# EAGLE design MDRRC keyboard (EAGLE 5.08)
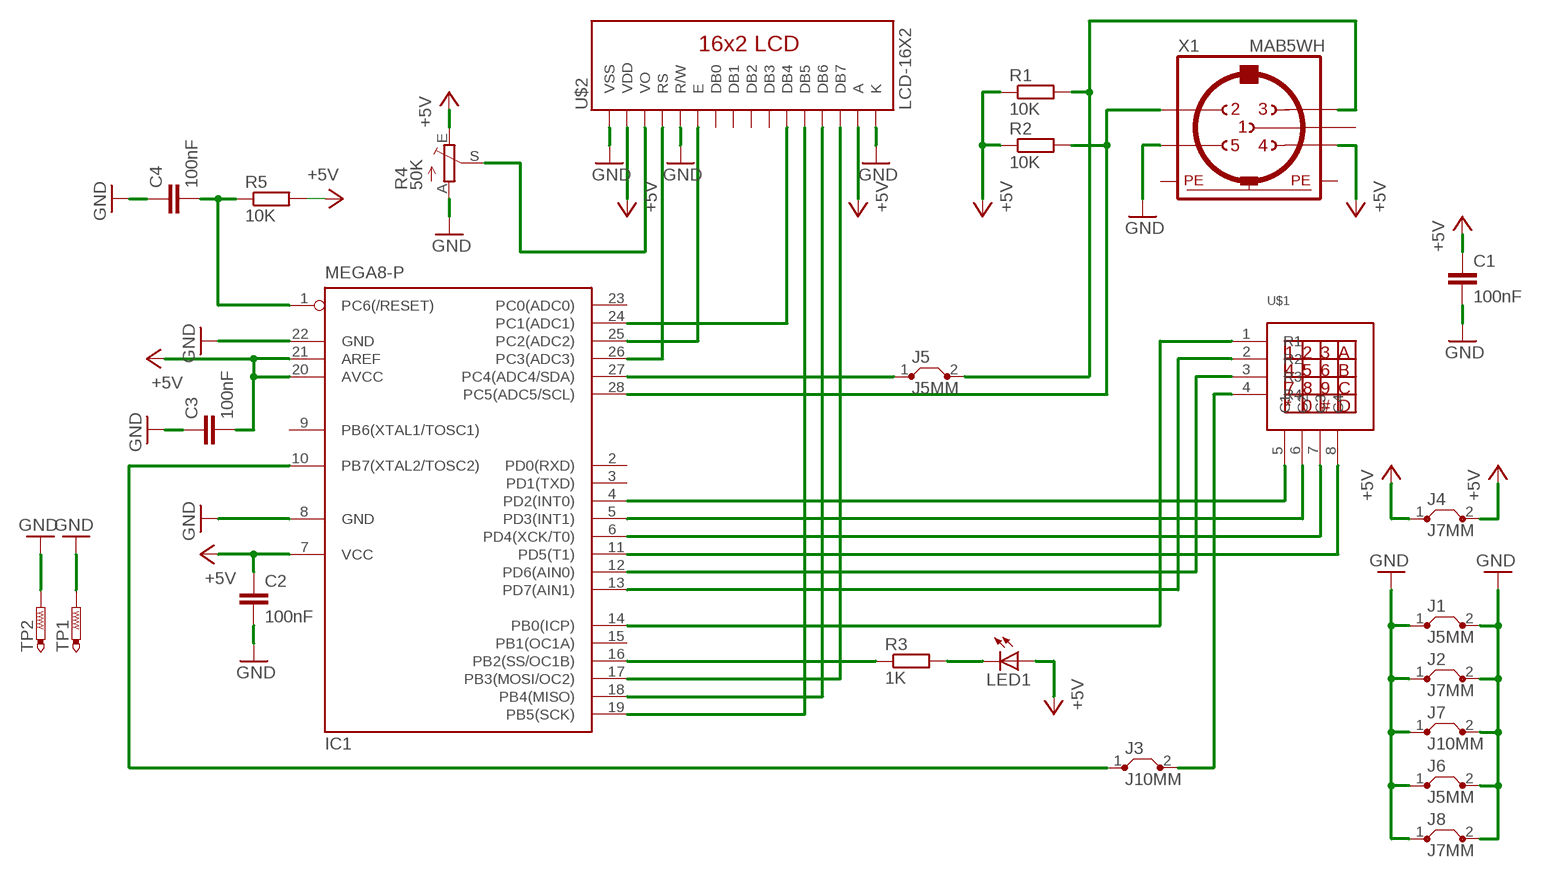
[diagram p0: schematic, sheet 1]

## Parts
C1  100nF  C-EU025-025X050  [C025-025X050]
C2  100nF  C-EU025-025X050  [C025-025X050]
C3  100nF  C-EU025-025X050  [C025-025X050]
C4  100nF  C-EU025-025X050  [C025-025X050]
IC1  MEGA8-P  [DIL28-3]
J1  J5MM  [05]
J2  J7MM  [07]
J3  J10MM  [10]
J4  J7MM  [07]
J5  J5MM  [05]
J6  J5MM  [05]
J7  J10MM  [10]
J8  J7MM  [07]
LED1  LED3MM  [LED3MM]
R1  10K  R-EU_0207/12  [0207/12]
R2  10K  R-EU_0207/12  [0207/12]
R3  1K  R-EU_0207/12  [0207/12]
R4  50K  TRIM_EU-CA6V  [CA6V]
R5  10K  R-EU_0207/15  [0207/15]
TP1  PTR1PAD1-13Y  [P1-13Y]
TP2  PTR1PAD1-13Y  [P1-13Y]
U$1  KEYPAD4X4  [KEYPAD4X4]
U$2  LCD-16X2  [LCD-16X2]
X1  MAB5WH  [MAB5WH]

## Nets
+5V: C1.1 C2.1 C3.2 IC1.7(VCC) IC1.20(AVCC) IC1.21(AREF) J4.1 J4.2 LED1.A R1.1 R2.1 R4.E R5.2 U$2.2(VDD) U$2.15(A) X1.4
GND: C1.2 C2.2 C3.1 C4.1 IC1.8(GND) IC1.22(GND) J1.1 J1.2 J2.1 J2.2 J6.1 J6.2 J7.1 J7.2 J8.1 J8.2 R4.A TP1.TP TP2.TP U$2.1(VSS) U$2.5(R/W) U$2.16(K) X1.5
N$1: IC1.14(PB0(ICP)) U$1.1(R1)
N$2: IC1.13(PD7(AIN1)) U$1.2(R2)
N$3: IC1.12(PD6(AIN0)) U$1.3(R3)
N$4: IC1.10(PB7(XTAL2/TOSC2)) J3.1
N$5: IC1.4(PD2(INT0)) U$1.5(C1)
N$6: IC1.5(PD3(INT1)) U$1.6(C2)
N$7: IC1.6(PD4(XCK/T0)) U$1.7(C3)
N$8: IC1.11(PD5(T1)) U$1.8(C4)
N$10: J5.2 R1.2 X1.3
N$11: IC1.25(PC2(ADC2)) U$2.6(E)
N$12: IC1.26(PC3(ADC3)) U$2.4(RS)
N$13: IC1.24(PC1(ADC1)) U$2.11(DB4)
N$14: IC1.19(PB5(SCK)) U$2.12(DB5)
N$15: IC1.18(PB4(MISO)) U$2.13(DB6)
N$16: IC1.17(PB3(MOSI/OC2)) U$2.14(DB7)
N$17: IC1.16(PB2(SS/OC1B)) R3.1
N$18: LED1.K(C) R3.2
N$19: R4.S U$2.3(VO)
N$20: J3.2 U$1.4(R4)
N$21: IC1.27(PC4(ADC4/SDA)) J5.1
N$22: C4.2 IC1.1(PC6(/RESET)) R5.1
N$23: IC1.28(PC5(ADC5/SCL)) R2.2 X1.2
Unconnected: IC1.2(PD0(RXD)) IC1.3(PD1(TXD)) IC1.9(PB6(XTAL1/TOSC1)) IC1.15(PB1(OC1A)) IC1.23(PC0(ADC0)) U$2.7(DB0) U$2.8(DB1) U$2.9(DB2) U$2.10(DB3) X1.1

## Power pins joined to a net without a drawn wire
PE: X1.PE X1.PE@(PE)

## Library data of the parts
C1-C4 = rcl:C-EU: CAPACITOR, European symbol
IC1 = atmel:MEGA8-P: MICROCONTROLLER 8 Kbytes FLASH, 1 kbytes SRAM, 512 bytes EEPROM, USART, 4-channel 10 bit ADC, 2-channel 8 bit ADC Pin compatible with Atmega48, ATMega88, ATMega168 Source: avr.lbr
J1-J8 = jumper:J: Bridge
LED1 = led:LED: LED
R1-R3 R5 = rcl:R-EU_: RESISTOR, European symbol
R4 = pot:TRIM_EU-: POTENTIOMETER
TP1 TP2 = testpad:PTR1: TEST PIN
U$1 = keypad4x4_ece:KEYPAD4X4
U$2 = SparkFun:LCD-16X2
X1 = con-hirschmann:MAB5WH: Female CONNECTOR 5 pins with shield, horizontal (DIN 45327)

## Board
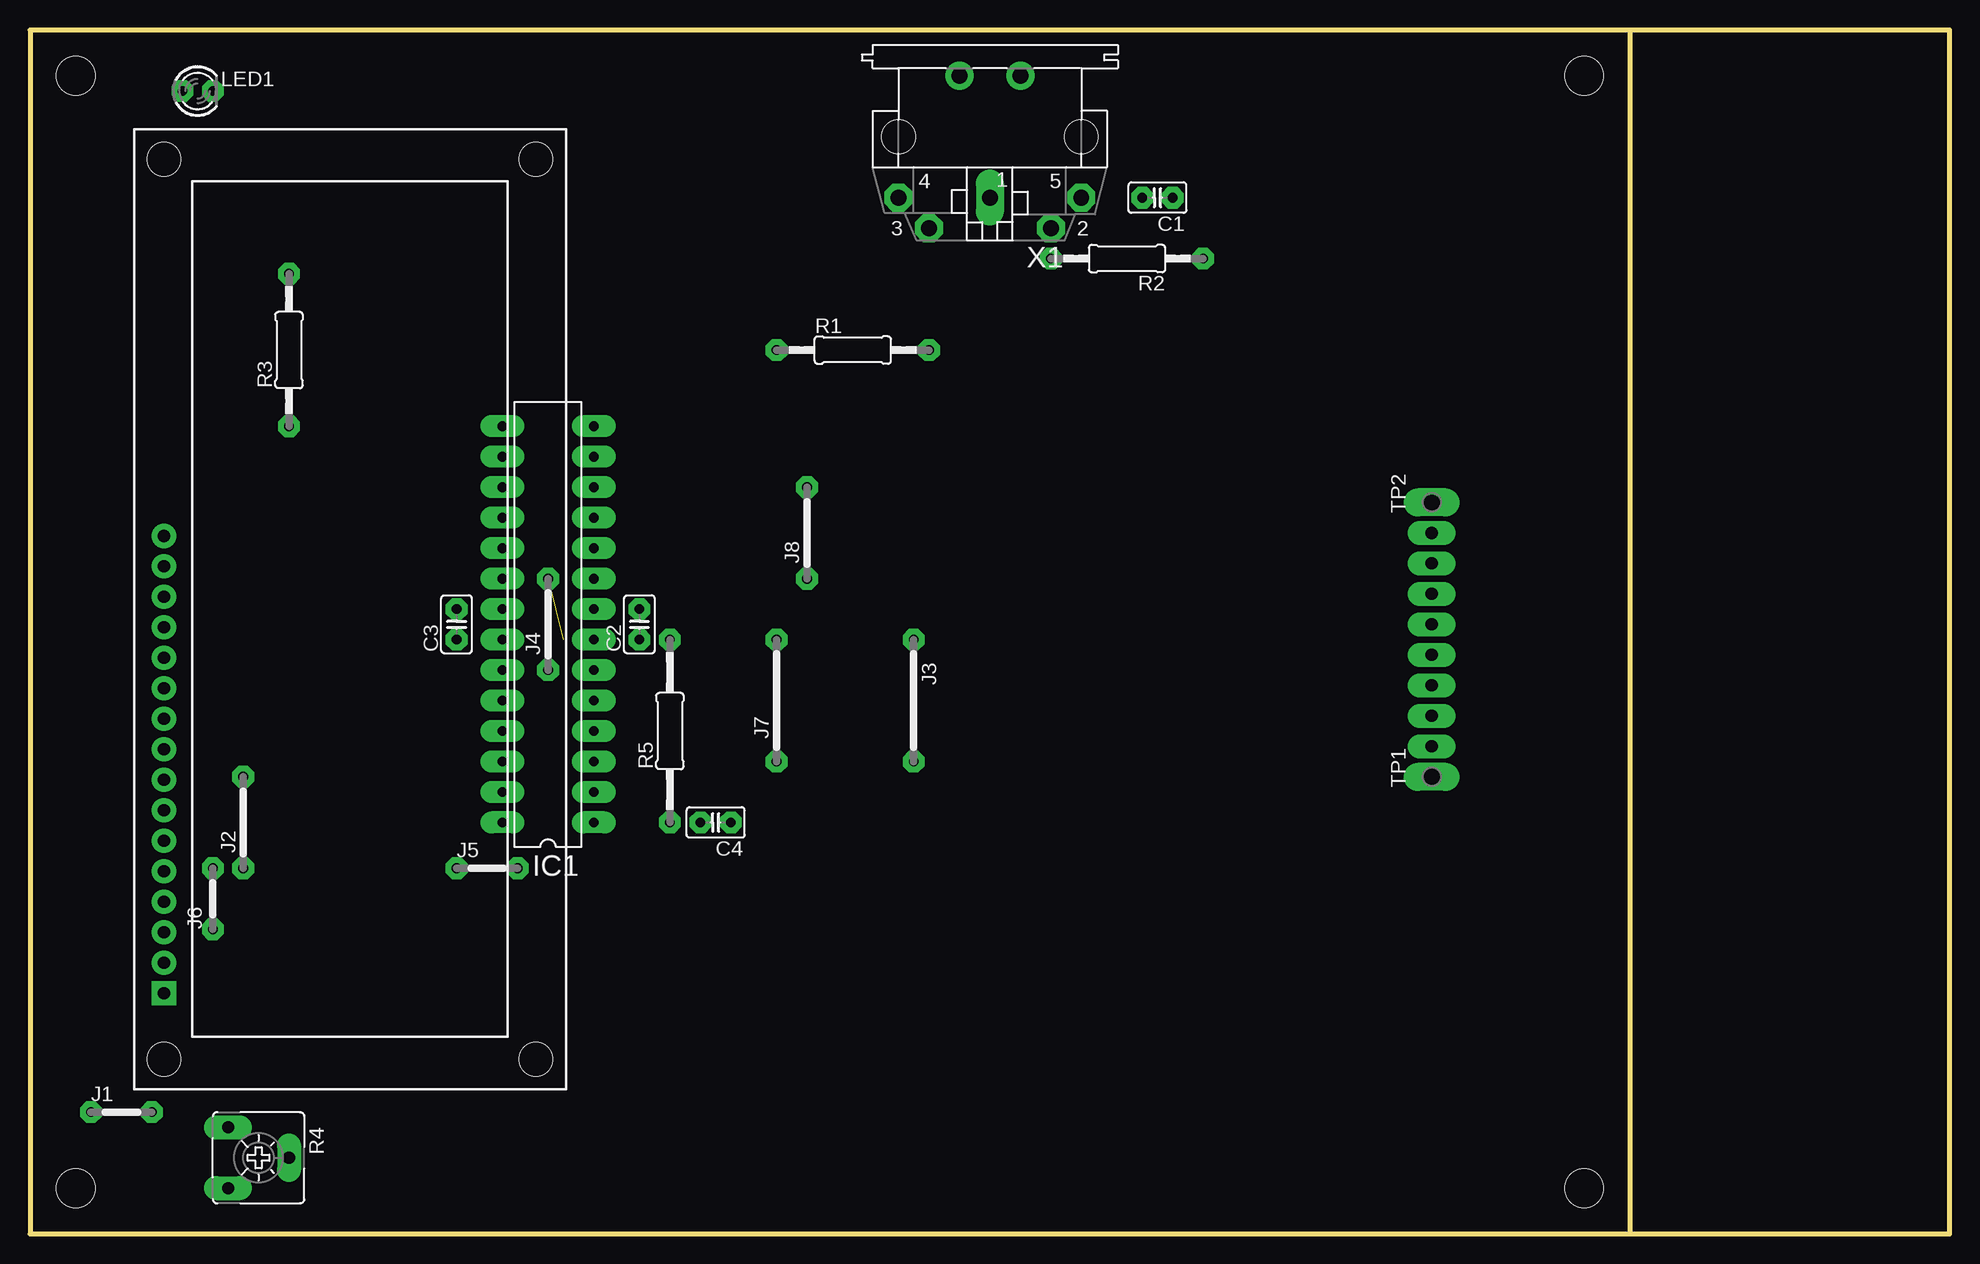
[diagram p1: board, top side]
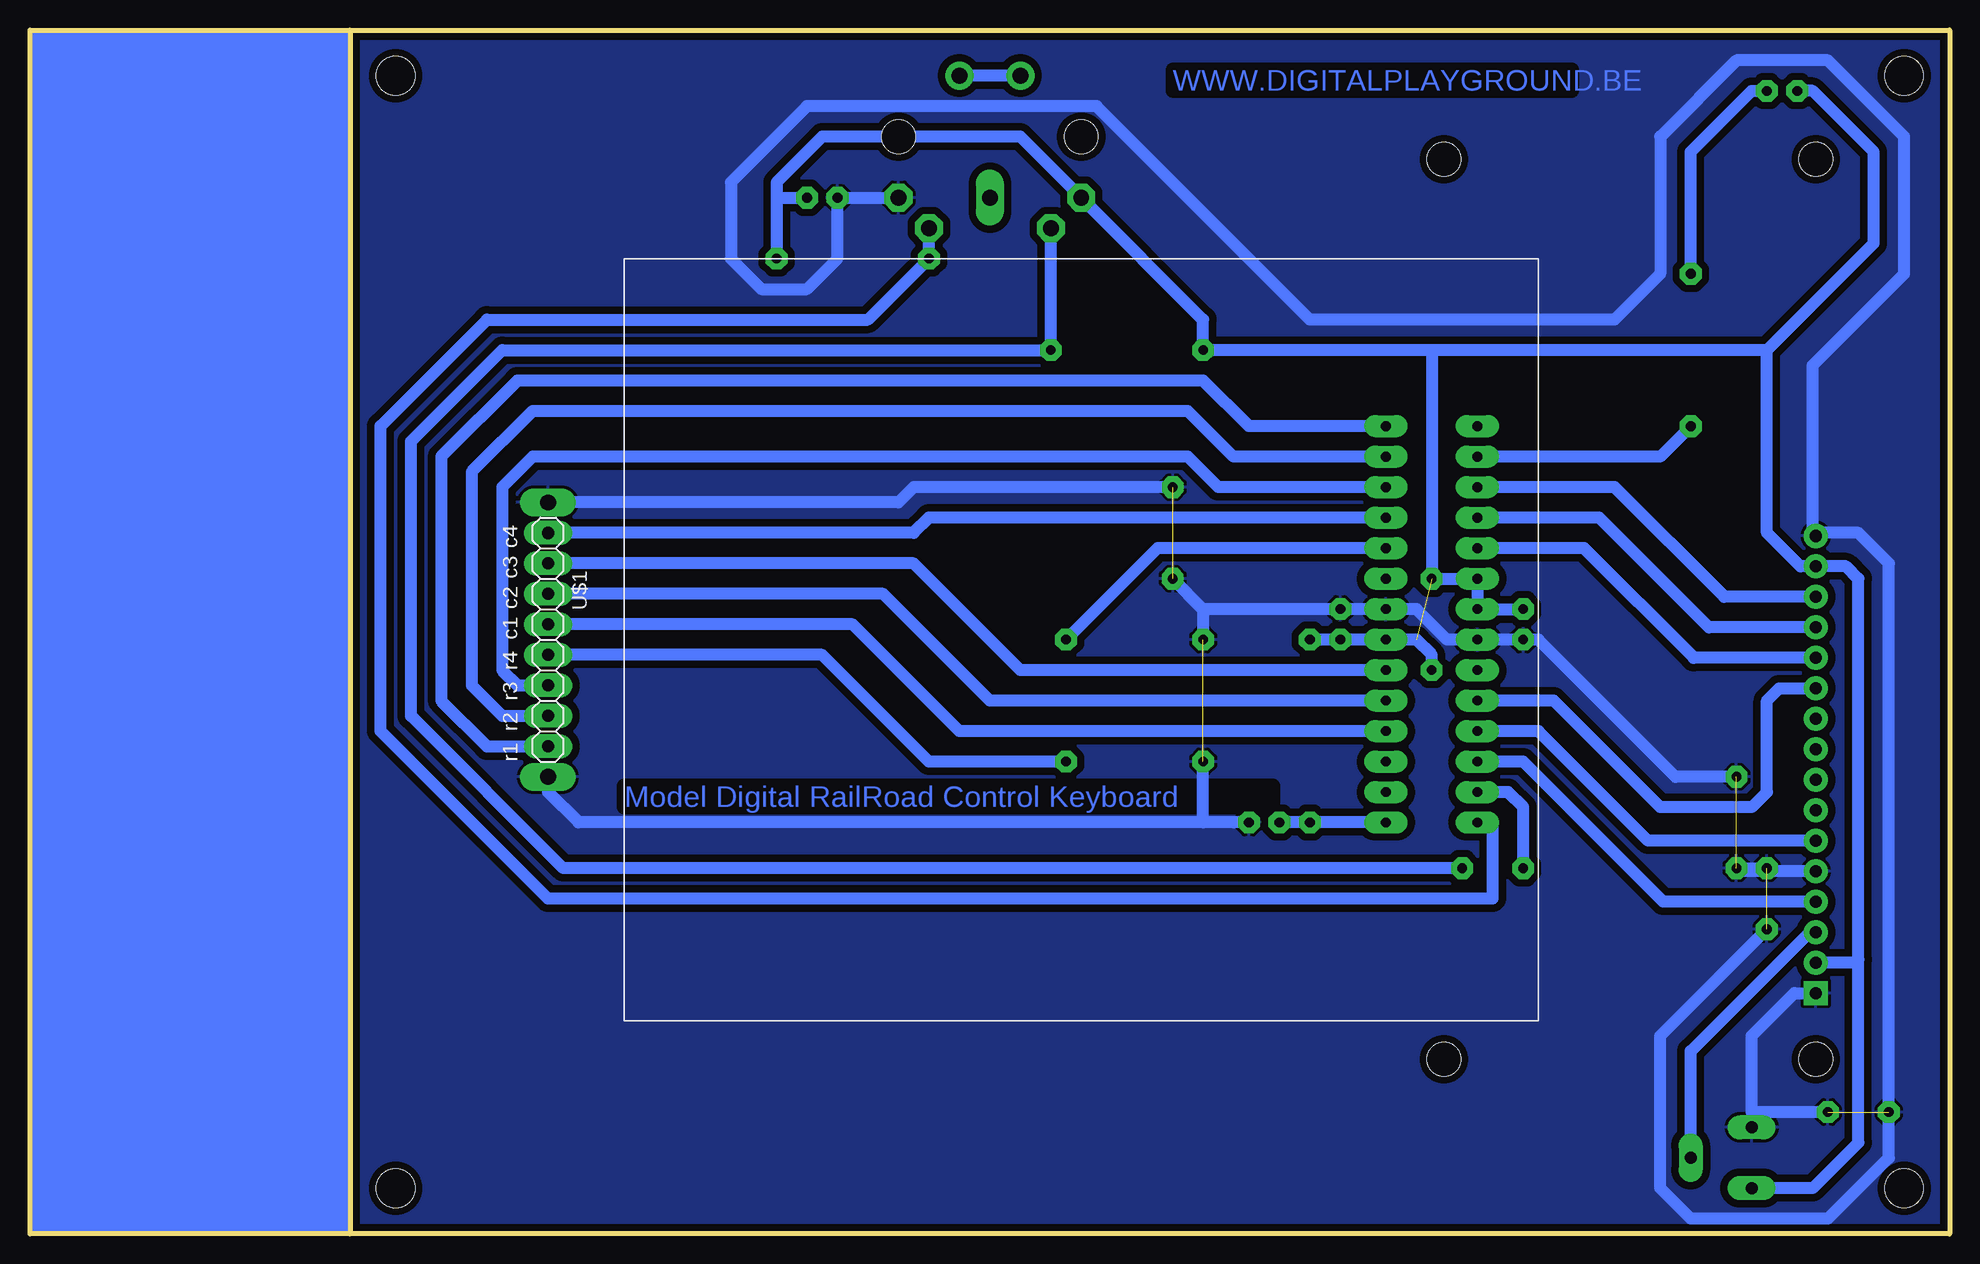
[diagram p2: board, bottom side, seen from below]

Size 160.02 x 100.33 mm. Coordinates in mm from the lower left corner, seen from the top.
Outline: 133.35,0 0,0 0,100.33 133.35,100.33
Outline: 133.35,0 160.02,0 160.02,100.33 133.35,100.33
Outline: 133.35,100.33 133.35,0
Copper layers (1*16): Top 0.8mm / dielectric 1.3mm / Bottom 0.8mm
Design rules "DRC settings smallest": minimum track width 0.8mm, minimum drill 24mil, track to track 0.2mm, track to pad 0.2mm, pad to pad 0.2mm, via to via 0.2mm, smd to smd 8mil, copper to edge 0.3mm, drill to drill 0.3mm, minimum pad ring 0.5mm, minimum via ring 1mm, stop-mask expansion 4mil, vias tented up to drill 0mil, thermal gap 10mil
Holes 3.2 mm at 3.81,96.52 3.81,3.81 129.54,96.52 129.54,3.81

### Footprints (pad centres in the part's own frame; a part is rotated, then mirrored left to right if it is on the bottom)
C025-025X050 = drill 0.813 octagon: 1 -1.27,0; 2 1.27,0
DIL28-3 = drill 0.813 long: 1 -16.51,-3.81; 2 -13.97,-3.81; 3 -11.43,-3.81; 4 -8.89,-3.81; 5 -6.35,-3.81; 6 -3.81,-3.81; 7 -1.27,-3.81; 8 1.27,-3.81; 9 3.81,-3.81; 10 6.35,-3.81; 11 8.89,-3.81; 12 11.43,-3.81; 13 13.97,-3.81; 14 16.51,-3.81; 15 16.51,3.81; 16 13.97,3.81; 17 11.43,3.81; 18 8.89,3.81; 19 6.35,3.81; 20 3.81,3.81; 21 1.27,3.81; 22 -1.27,3.81; 23 -3.81,3.81; 24 -6.35,3.81; 25 -8.89,3.81; 26 -11.43,3.81; 27 -13.97,3.81; 28 -16.51,3.81
05 = drill 0.813 pad 1.6 octagon: 1 -2.54,0; 2 2.54,0
07 = drill 0.813 pad 1.6 octagon: 1 -3.81,0; 2 3.81,0
10 = drill 0.813 pad 1.6 octagon: 1 -5.08,0; 2 5.08,0
LED3MM = drill 0.813 octagon: A -1.27,0; K 1.27,0
0207/12 = drill 0.813 octagon: 1 -6.35,0; 2 6.35,0
CA6V = drill 1.016 long: A -2.54,-2.54; E 2.54,-2.54; S 0,2.54
0207/15 = drill 0.813 octagon: 1 -7.62,0; 2 7.62,0
P1-13Y = drill 1.321 pad 1.905 long: TP 0,0
KEYPAD4X4 = drill 1.016 long: 1 -13.97,1.27; 2 -11.43,1.27; 3 -8.89,1.27; 4 -6.35,1.27; 5 -3.81,1.27; 6 -1.27,1.27; 7 1.27,1.27; 8 3.81,1.27
LCD-16X2 = drill 1.016 square: 1 -32,15.5 | drill 1.016 round: 2 -29.46,15.5; 3 -26.92,15.5; 4 -24.38,15.5; 5 -21.84,15.5; 6 -19.3,15.5; 7 -16.76,15.5; 8 -14.22,15.5; 9 -11.68,15.5; 10 -9.14,15.5; 11 -6.6,15.5; 12 -4.06,15.5; 13 -1.52,15.5; 14 1.02,15.5; 15 3.56,15.5; 16 6.1,15.5 | hole 2.8: -37.5,15.5; -37.5,-15.5; 37.5,15.5; 37.5,-15.5
MAB5WH = drill 1.321 long: 1 0,5.08 | drill 1.321 octagon: 2 -5.08,7.62; 3 5.08,7.62; 4 7.62,5.08; 5 -7.62,5.08 | drill 1.321 round: PE -2.54,-5.08; PE@ 2.54,-5.08 | hole 2.794: 7.62,0; -7.62,0

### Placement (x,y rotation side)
C1  93.98,86.36 180 top
C2  50.8,50.8 90 top
C3  35.56,50.8 90 top
C4  57.15,34.29 180 top
IC1  43.18,50.8 90 top
J1  7.62,10.16 0 top
J2  17.78,34.29 90 top
J3  73.66,44.45 270 top
J4  43.18,50.8 90 top
J5  38.1,30.48 0 top
J6  15.24,27.94 90 top
J7  62.23,44.45 90 top
J8  64.77,58.42 90 top
LED1  13.97,95.25 0 top
R1  68.58,73.66 0 top
R2  91.44,81.28 180 top
R3  21.59,73.66 90 top
R4  19.05,6.35 270 top
R5  53.34,41.91 90 top
TP1  116.84,38.1 90 top
TP2  116.84,60.96 90 top
U$1  115.57,54.61 90 bottom
U$2  26.67,52.07 90 top
X1  80.01,91.44 180 top

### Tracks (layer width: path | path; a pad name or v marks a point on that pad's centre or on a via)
+5V  (1 unrouted)
  Bottom 1.016: C3.2 IC1.21 IC1.20 J4.2 43.18,73.66 | R4.E 11.43,3.81 7.62,7.62 7.62,22.86 | 7.62,22.86 7.62,54.61 8.64,55.63 U$2.15 12.45,55.63 15.24,58.42 15.24,73.66 | U$2.2 7.87,22.61 7.62,22.86 | 97.79,86.36 97.79,87.63 93.98,91.44 77.47,91.44 X1.4 62.23,76.2 R1.1 43.18,73.66 | 97.79,86.36 R2.1 | 97.79,86.36 C1.1 | R5.2 C2.1 IC1.7 44.45,49.53 43.18,48.26 J4.1 | LED1.A 11.43,95.25 6.35,90.17 6.35,82.55 15.24,73.66 | 15.24,73.66 43.18,73.66
GND  (5 unrouted)
  Bottom 1.016: U$2.1 12.95,20.07 16.51,16.51 16.51,10.16 | 16.51,10.16 R4.A | J1.2 16.51,10.16 | X1.5 C1.2 92.71,81.28 95.25,78.74 99.06,78.74 101.6,81.28 101.6,87.63 95.25,93.98 71.12,93.98 53.34,76.2 27.94,76.2 24.13,80.01 24.13,91.44 17.78,97.79 10.16,97.79 3.81,91.44 3.81,80.01 11.43,72.39 11.43,58.43 U$2.16 10.92,58.42 7.62,58.42 5.08,55.88 J1.1 5.08,6.35 10.16,1.27 21.59,1.27 24.13,3.81 24.13,16.51 J6.1 | 59.69,34.29 C4.1 62.23,34.29 | TP1.TP 116.84,36.83 114.3,34.29 62.23,34.29 | 62.23,34.29 J7.1 | TP2.TP 87.63,60.96 86.36,62.23 J8.2 | 62.23,52.07 J8.1 | 62.23,52.07 C2.2 IC1.8 44.45,52.07 41.91,49.53 IC1.22 C3.1 34.29,49.53 22.86,38.1 J2.2 | 62.23,52.07 J7.2 | U$2.5 17.53,30.23 J2.1 J6.2
  pour Bottom (isolate 0.61): 0,100.33 133.35,100.33 133.35,0 0,0
  pour Bottom (isolate 0.813): 0,100.33 133.35,100.33 133.35,0 0,0
N$1
  Bottom 1.016: U$1.1 121.92,40.64 125.73,44.45 125.73,64.77 119.38,71.12 62.23,71.12 58.42,67.31 IC1.14
N$2
  Bottom 1.016: U$1.2 120.65,43.18 123.19,45.72 123.19,63.5 118.11,68.58 63.5,68.58 59.69,64.77 IC1.13
N$3
  Bottom 1.016: IC1.12 60.96,62.23 63.5,64.77 118.11,64.77 120.65,62.23 120.65,46.99 119.38,45.72 U$1.3
N$4
  Bottom 1.016: IC1.10 66.04,57.15 J3.1
N$5
  Bottom 1.016: U$1.5 91.44,50.8 82.55,41.91 IC1.4
N$6
  Bottom 1.016: U$1.6 88.9,53.34 80.01,44.45 IC1.5
N$7
  Bottom 1.016: U$1.7 86.36,55.88 77.47,46.99 IC1.6
N$8
  Bottom 1.016: U$1.8 86.36,58.42 85.09,59.69 IC1.11
N$10
  Bottom 1.016: X1.3 R1.2 120.65,73.66 128.27,66.04 128.27,43.18 115.57,30.48 J5.2
N$11
  Bottom 1.016: U$2.6 25.15,32.77 34.29,41.91 IC1.25
N$12
  Bottom 1.016: U$2.4 23.88,27.69 35.56,39.37 IC1.26
N$13
  Bottom 1.016: IC1.24 33.02,44.45 24.13,35.56 16.51,35.56 15.24,36.83 15.24,44.45 14.22,45.47 U$2.11
N$14
  Bottom 1.016: U$2.12 21.34,48.01 30.48,57.15 IC1.19
N$15
  Bottom 1.016: U$2.13 20.07,50.55 29.21,59.69 IC1.18
N$16
  Bottom 1.016: U$2.14 18.8,53.09 27.94,62.23 IC1.17
N$17
  Bottom 1.016: IC1.16 24.13,64.77 R3.1
N$18
  Bottom 1.016: LED1.K 16.51,95.25 21.59,90.17 R3.2
N$19
  Bottom 1.016: U$2.3 11.68,25.15 21.59,15.24 R4.S
N$20
  Bottom 1.016: U$1.4 93.98,48.26 85.09,39.37 J3.2
N$21
  Bottom 1.016: IC1.27 36.83,36.83 35.56,35.56 J5.1
N$22
  Bottom 1.016: IC1.1 R5.1 C4.2
N$23
  Bottom 1.016: X1.2 R2.2 90.17,76.2 121.92,76.2 130.81,67.31 130.81,41.91 116.84,27.94 38.1,27.94 38.1,34.29 IC1.28
PE
  Bottom 1.016: X1.PE@ X1.PE
(copper drawn outside any net)
  shapes: Bottom area x1

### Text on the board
Bottom: WWW.DIGITALPLAYGROUND.BE | Model Digital RailRoad Control Keyboard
